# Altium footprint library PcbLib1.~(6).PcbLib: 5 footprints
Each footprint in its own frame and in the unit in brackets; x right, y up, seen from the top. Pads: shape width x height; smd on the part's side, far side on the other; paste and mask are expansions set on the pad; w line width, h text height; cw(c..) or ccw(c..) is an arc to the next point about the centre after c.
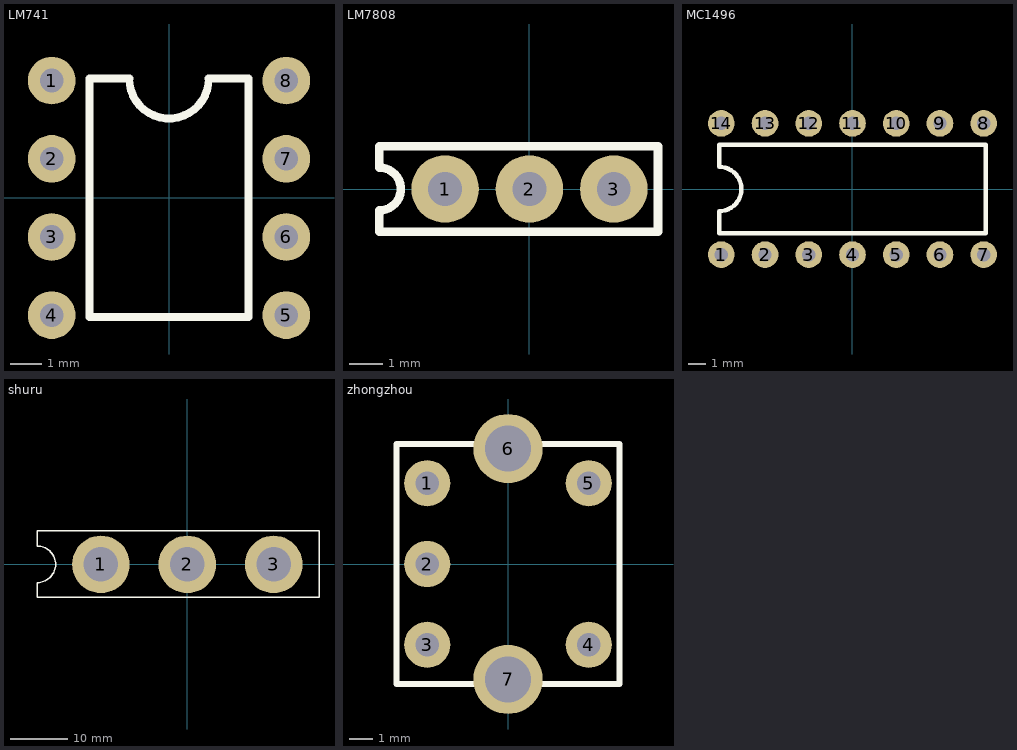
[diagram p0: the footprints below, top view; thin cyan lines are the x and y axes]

## LM741 [mil]
pads (8):
  round 60 hole 30: 1(-147.64,147.64) 2(-147.64,49.21) 3(-147.64,-49.21) 4(-147.64,-147.64) 5(147.64,-147.64) 6(147.64,-49.21) 7(147.64,49.21) 8(147.64,147.64)
Top Overlay:
  lines w10: -100,-150 -100,150 -50,150 ccw(c0,150) 50,150 100,150 100,-150 -100,-150

## LM7808 [mm]
pads (3):
  round 2 hole 1: 1(-2.5,0) 2(0,0) 3(2.5,0)
Top Overlay:
  lines w0.254: -4.445,-1.27 3.81,-1.27 3.81,1.27 -4.445,1.27 -4.445,0.635 cw(c-4.445,0) -4.445,-0.635 -4.445,-1.27

## MC1496 [mil]
pads (14):
  round 60 hole 30: 1(-295.28,-147.64) 2(-196.85,-147.64) 3(-98.43,-147.64) 4(0,-147.64) 5(98.43,-147.64) 6(196.85,-147.64) 7(295.28,-147.64) 8(295.28,147.64) 9(196.85,147.64) 10(98.43,147.64) 11(0,147.64) 12(-98.43,147.64) 13(-196.85,147.64) 14(-295.28,147.64)
Top Overlay:
  lines w10: -300,-100 300,-100 300,100 -300,100 -300,50 cw(c-300,0) -250,0 cw(c-300,0) -300,-50 -300,-100

## shuru [mm]
pads (3):
  round 10 hole 6: 1(-15,0) 2(0,0) 3(15,0)
Top Layer:
  lines w0.254: -26.035,5.839 -26.032,5.842
Top Overlay:
  lines w0.254: -26.038,3.178 cw(c-26.038,0) -22.86,0 cw(c-26.035,0) -26.035,-3.175 -26.035,-5.715 22.86,-5.715 22.86,5.842 -26.032,5.842 ; -26.035,3.178 -26.035,5.839

## zhongzhou [mm]
pads (7):
  round 2 hole 1: 1(-3.5,3.5) 2(-3.5,0) 3(-3.5,-3.5) 4(3.5,-3.5) 5(3.5,3.5)
  round 3 hole 2: 6(0,5) 7(0,-5)
Top Overlay:
  lines w0.254: -4.826,-5.207 -4.826,5.207 1.143,5.207 4.826,5.207 4.826,-5.207 -1.143,-5.207 -4.826,-5.207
